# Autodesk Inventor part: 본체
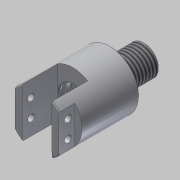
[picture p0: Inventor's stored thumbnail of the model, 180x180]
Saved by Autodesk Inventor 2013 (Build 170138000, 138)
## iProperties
Created: 2019-02
Part Number: 본체
Material: 알루미늄 6061
Document SubType Name: Modeling
Designer: dgall
Density: 2.71 g/cm^3
Mass: 345.864 g
Surface Area: 290.372 cm^2
Volume: 127.625 cm^3
Author: dgall
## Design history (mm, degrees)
sketch "스케치5"
  geometry: C1 r 29 at (0, 0); 1 further point
  constraints: 1 centre point, 1 coincident
  dimensions: "d12" = 58 diameter of C1
extrude "돌출3" new body sketch "스케치5" stored distance "d14" = 74; taper "d15" = 0 deg
sketch "스케치6"
  geometry: L1 (14.984, 24.829)-(15.016, -24.81); L2 (-14.984, -24.829)-(-15.016, 24.81); A1 r 29 centre (0, 0) between (-15.016, 24.81) and (15.016, -24.81) reference; A2 r 29 centre (0, 0) between (-15.016, 24.81) and (15.016, -24.81) reference; A3 r 29 centre (0, 0) between (-14.984, -24.829) and (15.016, -24.81); A4 r 29 centre (0, 0) between (14.984, 24.829) and (-15.016, 24.81)
  constraints: 11 point on circle, 4 end point, 2 centre point, 1 coincident, 1 parallel
  dimensions: "d17" = 30 distance between parallel lines of L1 L2; "d19" = 15 distance from line of A1.centre L2; "d20" = 24.80968 vertical distance of L1.end A1.centre
extrude "돌출4" cut sketch "스케치6" distance "d21" = 36; taper "d22" = 0 deg
node "작업 평면3"
sketch "스케치7"
  geometry: L1 (-37, 24.81)-(-37, -24.829) reference; L2 (-37, 24.81)-(-21, 24.81); L3 (-21, 24.81)-(-21, -24.829); L4 (-21, -24.829)-(-37, -24.829); L5 (-37, -24.829)-(-37, 24.81); 1 further point
  constraints: 8 end point, 2 parallel, 1 horizontal, 1 perpendicular, 1 point on line
  dimensions: "d24" = 16 distance between parallel lines of L3 L1; "d25" = 0 distance from line of L1.start L2; "d26" = 0 distance from line of L1.end L4
extrude "돌출5" cut sketch "스케치7" distance "d27" = 36; taper "d28" = 0 deg
sketch "스케치9"
  geometry: L1 (-1, -24.829)-(-1, 24.81) reference; L2 (-1, -0.01)-(36.922, -0.01); L3 (-1, -0.01)-(-1, 13.99); L4 (-1, 13.99)-(1.65, 13.99); L5 (1.65, 13.99)-(1.65, 16.19); L6 (2.45, 16.99)-(5.55, 16.99); L7 (6.35, 16.19)-(6.35, 13.99); L8 (6.35, 13.99)-(10.65, 13.99); L9 (10.65, 13.99)-(10.65, 16.19); L10 (11.45, 16.99)-(14.55, 16.99); L11 (15.35, 16.19)-(15.35, 13.99); L12 (15.35, 13.99)-(19, 13.99); L13 (19, 13.99)-(19, 15.99); L14 (4, 16.99)-(4, -0.01); L15 (13, 16.99)-(13, -0.01); L16 (19, 15.99)-(26, 15.99); L17 (26, 15.99)-(26, -0.01); A1 r 0.8 centre (2.45, 16.19) between (2.45, 16.99) and (1.65, 16.19); A2 r 0.8 centre (5.55, 16.19) between (6.35, 16.19) and (5.55, 16.99); A3 r 0.8 centre (11.45, 16.19) between (11.45, 16.99) and (10.65, 16.19); A4 r 0.8 centre (14.55, 16.19) between (15.35, 16.19) and (14.55, 16.99); 5 further points
  constraints: 32 end point, 12 point on line, 8 point on circle, 8 tangent, 7 perpendicular, 6 parallel, 4 centre point, 3 midpoint, 2 collinear, 2 equal radius
  dimensions: "d32" = 28 diameter of L4 L2; "d33" = 34 diameter of L6 L2; "d34" = 5 distance between parallel lines of L14 L3; "d35" = 4.7 distance between parallel lines of L7 L5; "d36" = 28 diameter of L8 L2; "d37" = 4.7 distance between parallel lines of L11 L9; "d38" = 9 distance between parallel lines of L15 L14; "d39" = 34 diameter of L10 L2; "d40" = 28 diameter of L12 L2; "d41" = 32 diameter of L16 L2; "d42" = 7 distance between parallel lines of L17 L13; "d44" = 20 distance between parallel lines of L13 L1; "d70" = 0.8 radius of A1; "d71" = 0.8 radius of A2
revolve "회전1" sketch "스케치9" stored, may be unused: angle "d45" = 90 deg
sketch "스케치10"
  geometry: C1 r 29 at (0, 0) reference; C2 r 14 at (0, 0)
  constraints: 1 centre point, 1 coincident
  dimensions: "d46" = 28 diameter of C2
extrude "돌출6" join sketch "스케치10" distance "d48" = 5; taper "d49" = 0 deg
sketch "스케치11"
  geometry: C1 r 14 at (0, 0) reference; C2 r 15 at (0, 0)
  constraints: 1 centre point, 1 coincident
  dimensions: "d50" = 30 diameter of C2
extrude "돌출7" join sketch "스케치11" distance "d52" = 29; taper "d53" = 0 deg
sketch "스케치12"
  geometry: C1 r 15 at (0, 0) reference; C2 r 7 at (0, 0)
  constraints: 1 centre point, 1 coincident
  dimensions: "d54" = 14 diameter of C2
extrude "돌출8" cut sketch "스케치12" distance "d56" = 22; taper "d57" = 0 deg
sketch "스케치13"
  geometry: C1 r 7 at (0, 0) reference; C2 r 4 at (0, 0)
  constraints: 1 centre point, 1 coincident
  dimensions: "d58" = 8 diameter of C2
extrude "돌출9" cut sketch "스케치13" stored distance "d60" = 22; taper "d61" = 0 deg
chamfer "모따기1" distance "d62" = 1; stored, may be unused: second distance "d63" = 2, angle "d64" = 45 deg
chamfer "모따기2" distance "d65" = 1; stored, may be unused: second distance "d66" = 2, angle "d67" = 45 deg
chamfer "모따기3" distance "d72" = 1; stored, may be unused: second distance "d73" = 2, angle "d74" = 45 deg
feature "스레드1" dims "d75" = 10, "d76" = 0
chamfer "모따기4" distance "d77" = 1; stored, may be unused: second distance "d78" = 2, angle "d79" = 45 deg
chamfer "모따기5" distance "d80" = 1; stored, may be unused: second distance "d81" = 2, angle "d82" = 45 deg
feature "스레드2" dims "d83" = 18, "d84" = 0
chamfer "모따기6" distance "d85" = 1; stored, may be unused: second distance "d86" = 2, angle "d87" = 45 deg
sketch "스케치14"
  geometry: L1 (36.215, -16)-(1.574, -16) reference; C1 r 3.5 at (9.894, -7); C2 r 3.5 at (27.894, -7); 1 further point
  constraints: 2 centre point
  dimensions: "d88" = 9 distance from line of C1.centre L1; "d89" = 9 distance from line of C2.centre L1; "d90" = 9 horizontal distance of point (18.894, 21) C1.centre; "d91" = 9 horizontal distance of C2.centre point (18.894, 21); "d92" = 7 diameter of C1; "d93" = 7 diameter of C2
extrude "돌출10" cut sketch "스케치14" stored distance "d94" = 7; taper "d95" = 0 deg
sketch "스케치15"
  geometry: L1 (17.321, -37)-(-17.321, -37) reference; C1 r 3.5 at (9, -28); C2 r 3.5 at (-9, -28) reference; C3 r 3.5 at (-9, -28); 1 further point
  constraints: 2 centre point, 1 coincident
  dimensions: "d96" = 7 diameter of C3; "d98" = 7 diameter of C1; "d99" = 18 distance of C3.centre C1.centre; "d100" = 9 distance from line of L1 C1.centre
extrude "돌출11" cut sketch "스케치15" stored distance "d101" = 7; taper "d102" = 0 deg
node "작업 평면4"
sketch "스케치16"
  geometry: L1 (9, -5)-(-31, -5); L2 (-31, -5)-(-31, 5); L3 (-31, 5)-(9, 5); L4 (9, 5)-(9, -5); L5 (9, -5)-(-31, 5); L6 (-31, -5)-(9, 5); L7 (9, 0)-(-31, 0); L8 (-11, -5)-(-11, 5); L9 (-36, 29)-(-36, -29) reference; 2 further points
  constraints: 16 end point, 6 midpoint, 2 parallel, 1 horizontal, 1 perpendicular
  dimensions: "d104" = 40 distance between parallel lines of L2 L4; "d106" = 10 distance between parallel lines of L3 L1; "d107" = 0 distance from line of point (0, 0) L7; "d108" = 5 distance between parallel lines of L9 L2
extrude "돌출12" join sketch "스케치16" stored distance "d109" = 7; taper "d110" = 0 deg
sketch "스케치17"
  geometry: L1 (5, -9)-(-5, -9) reference; L2 (-1.991, -5.592)-(-1.991, 27.592); L3 (-1.991, 27.592)-(1.991, 27.592); L4 (1.991, 27.592)-(1.991, -5.592); L5 (1.991, -5.592)-(-1.991, -5.592); L6 (0, -5.592)-(0, 27.592); L7 (-1.991, 11)-(1.991, 11); 1 further point
  constraints: 4 end point, 4 midpoint, 2 other
  dimensions: "d111" = 0 distance from line of point (0, 0) L6; "d112" = 20 distance between parallel lines of L7 L1
extrude "돌출13" join sketch "스케치17" distance "d113" = 0.5; taper "d114" = 0 deg
node "솔리드2"
mirror "대칭1"
other parameters: "d23" = 22
